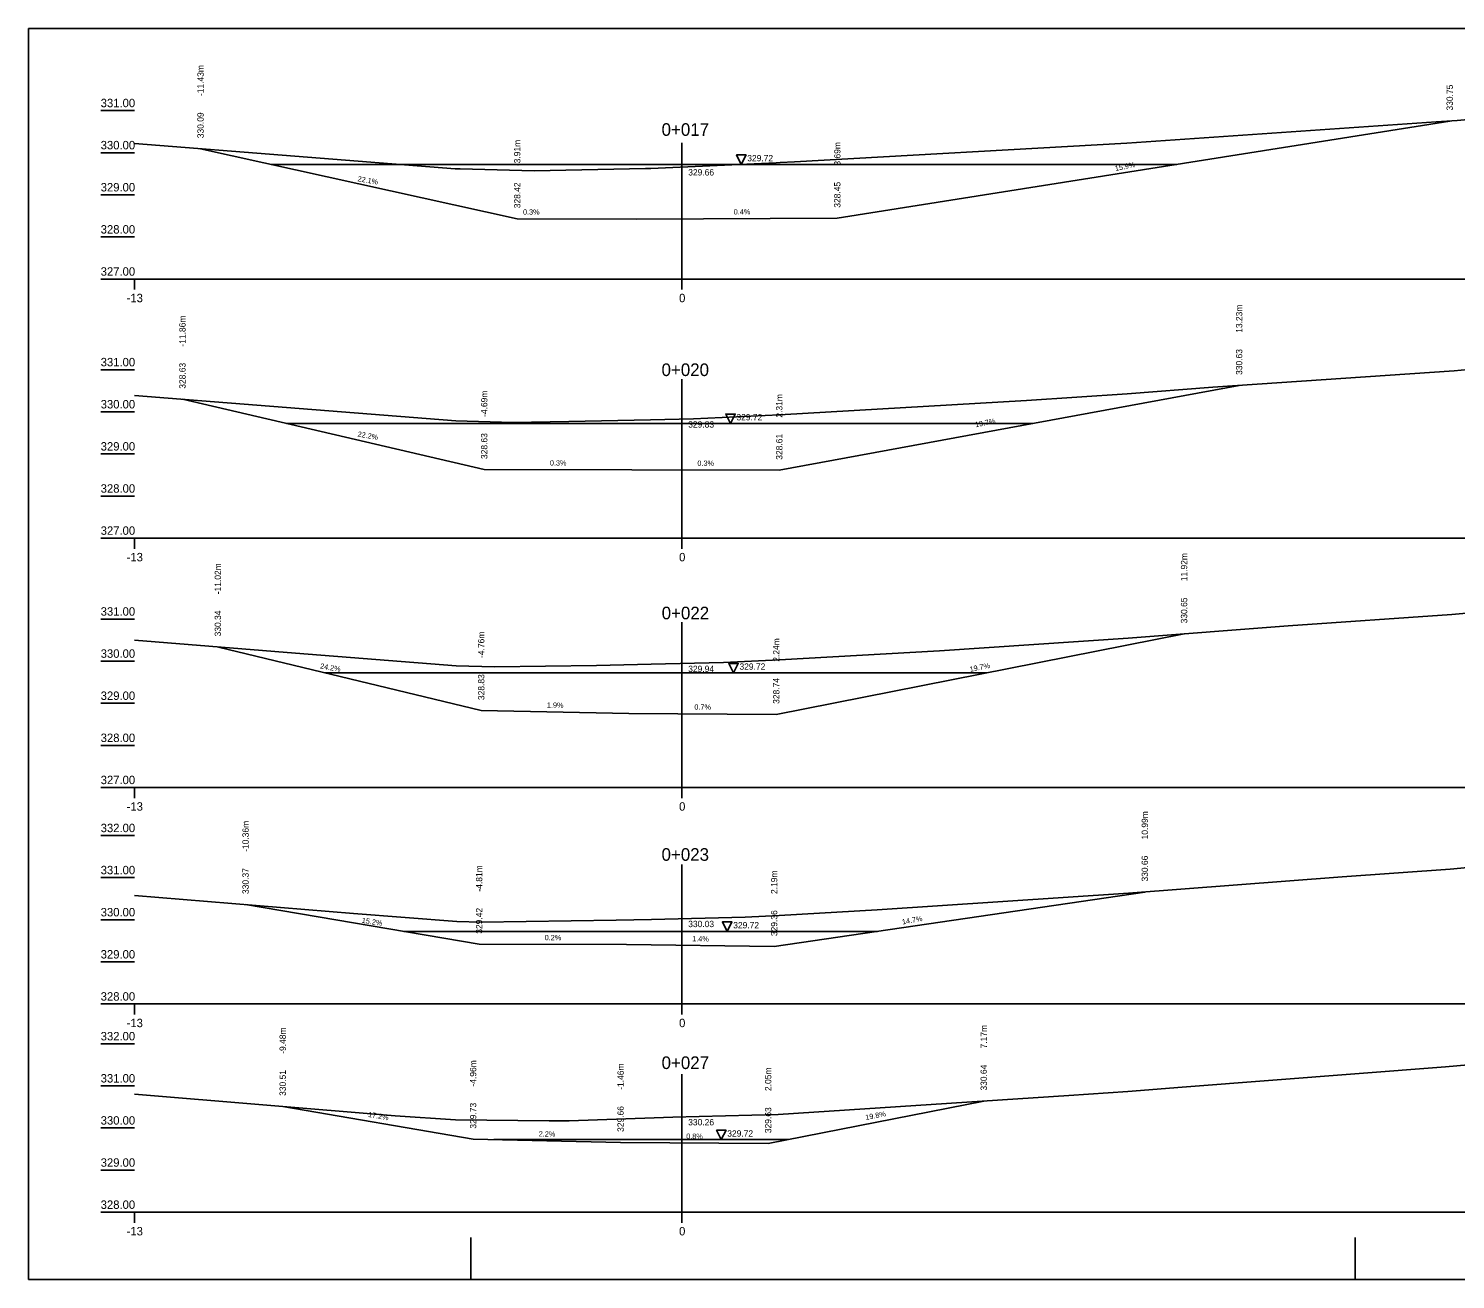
# Model space of a CAD drawing. Extents: x -557757.2 to -557704.7, y -1163075.9 to -1163046.2.
# Drawn here: x -557757.2 to -557723.32, y -1163075.94 to -1163046.24 of the extents above; entities that cross this region are included whole.
import ezdxf

# ---------------------------------------------------------------- set-up
doc = ezdxf.new("R2010")
doc.units = 0
for name, color, linetype in [('16', 7, 'Continuous'), ('21', 7, 'Continuous'), ('28', 7, 'Continuous'), ('59', 7, 'Continuous'), ('Body pricny rez', 7, 'Continuous'), ('Popis pricneho profilu', 7, 'Continuous')]:
    doc.layers.add(name, color=color, linetype=linetype)

msp = doc.modelspace()

# ---------------------------------------------------------------- linework, layer by layer
for p, q in [((-557704.7, -1163046.243), (-557757.2, -1163046.243)), ((-557757.2, -1163046.243), (-557757.2, -1163075.943)), ((-557746.7, -1163075.943), (-557746.7, -1163074.943)), ((-557725.7, -1163075.943), (-557725.7, -1163074.943)), ((-557757.2, -1163075.943), (-557704.7, -1163075.943))]:
    msp.add_line(p, q)
for points in [[(-557754.687, -1163048.974), (-557747.074, -1163049.572), (-557746.951, -1163049.573), (-557746.95, -1163049.573), (-557745.198, -1163049.623), (-557742.55, -1163049.568), (-557742.425, -1163049.567), (-557739.452, -1163049.428), (-557739.355, -1163049.423), (-557739.014, -1163049.405), (-557731.126, -1163048.962), (-557723.775, -1163048.462), (-557723.281, -1163048.428), (-557721.687, -1163048.284)], [(-557737.997, -1163050.747), (-557723.457, -1163048.44)], [(-557742.764, -1163050.767), (-557745.597, -1163050.76), (-557753.117, -1163049.097)], [(-557751.441, -1163049.468), (-557729.936, -1163049.468)], [(-557742.764, -1163050.767), (-557737.997, -1163050.747)], [(-557742.764, -1163050.767), (-557737.997, -1163050.747)], [(-557754.687, -1163054.952), (-557752.781, -1163055.108), (-557747.058, -1163055.556), (-557745.702, -1163055.595), (-557744.371, -1163055.575), (-557742.431, -1163055.534), (-557741.41, -1163055.51), (-557739.368, -1163055.414), (-557733.503, -1163055.076), (-557731.111, -1163054.918), (-557729.08, -1163054.759), (-557723.35, -1163054.37), (-557721.687, -1163054.213)], [(-557739.375, -1163056.731), (-557728.457, -1163054.717)], [(-557742.877, -1163056.723), (-557746.38, -1163056.714), (-557753.547, -1163055.045)], [(-557751.077, -1163055.62), (-557733.353, -1163055.62)], [(-557742.877, -1163056.723), (-557746.38, -1163056.714)], [(-557742.877, -1163056.723), (-557739.375, -1163056.731)], [(-557742.877, -1163056.723), (-557739.375, -1163056.731)], [(-557754.687, -1163060.763), (-557750.861, -1163061.076), (-557747.043, -1163061.376), (-557746.139, -1163061.401), (-557743.716, -1163061.365), (-557742.418, -1163061.338), (-557740.697, -1163061.298), (-557739.372, -1163061.235), (-557735.569, -1163061.016), (-557731.093, -1163060.72), (-557727.294, -1163060.423), (-557723.406, -1163060.159), (-557721.687, -1163059.997)], [(-557739.446, -1163062.527), (-557729.764, -1163060.616)], [(-557739.446, -1163062.527), (-557729.764, -1163060.616)], [(-557746.451, -1163062.437), (-557752.687, -1163060.927)], [(-557750.154, -1163061.54), (-557734.447, -1163061.54)], [(-557742.948, -1163062.502), (-557746.451, -1163062.437)], [(-557742.948, -1163062.502), (-557746.451, -1163062.437)], [(-557742.948, -1163062.502), (-557739.446, -1163062.527)], [(-557742.948, -1163062.502), (-557739.446, -1163062.527)], [(-557754.687, -1163066.825), (-557749.483, -1163067.251), (-557747.032, -1163067.443), (-557746.452, -1163067.459), (-557743.246, -1163067.412), (-557742.409, -1163067.395), (-557740.184, -1163067.343), (-557739.375, -1163067.304), (-557737.051, -1163067.171), (-557731.081, -1163066.775), (-557726.013, -1163066.38), (-557723.447, -1163066.205), (-557721.687, -1163066.039)], [(-557739.497, -1163068.041), (-557730.697, -1163066.745)], [(-557746.502, -1163067.984), (-557752.047, -1163067.041)], [(-557748.29, -1163067.68), (-557737.045, -1163067.68)], [(-557742.999, -1163067.992), (-557746.502, -1163067.984)], [(-557742.999, -1163067.992), (-557746.502, -1163067.984)], [(-557742.999, -1163067.992), (-557739.497, -1163068.041)], [(-557742.999, -1163067.992), (-557739.497, -1163068.041)], [(-557754.687, -1163071.547), (-557748.492, -1163072.055), (-557747.066, -1163072.157), (-557744.839, -1163072.175), (-557744.64, -1163072.177), (-557744.365, -1163072.179), (-557742.347, -1163072.108), (-557741.902, -1163072.09), (-557739.398, -1163072.03), (-557732.496, -1163071.574), (-557731.099, -1163071.478), (-557729.805, -1163071.381), (-557723.555, -1163070.894), (-557722.212, -1163070.775), (-557721.687, -1163070.726)], [(-557739.64, -1163072.719), (-557734.521, -1163071.708)], [(-557739.64, -1163072.719), (-557734.521, -1163071.708)], [(-557746.645, -1163072.613), (-557751.166, -1163071.835)], [(-557746.645, -1163072.613), (-557751.166, -1163071.835)], [(-557743.142, -1163072.69), (-557746.645, -1163072.613)], [(-557743.142, -1163072.69), (-557746.645, -1163072.613)], [(-557746.151, -1163072.624), (-557739.157, -1163072.624)], [(-557743.142, -1163072.69), (-557739.64, -1163072.719)], [(-557743.142, -1163072.69), (-557739.64, -1163072.719)]]:
    msp.add_lwpolyline(points)
for points in [[(-557740.277, -1163049.468), (-557740.389, -1163049.243), (-557740.164, -1163049.243)], [(-557740.534, -1163055.62), (-557740.647, -1163055.395), (-557740.422, -1163055.395)], [(-557740.463, -1163061.54), (-557740.575, -1163061.315), (-557740.35, -1163061.315)], [(-557740.61, -1163067.68), (-557740.723, -1163067.455), (-557740.498, -1163067.455)], [(-557740.752, -1163072.624), (-557740.864, -1163072.399), (-557740.639, -1163072.399)]]:
    msp.add_lwpolyline(points, close=True)
at = {"layer": '16'}
for p, q in [((-557754.687, -1163052.191), (-557721.687, -1163052.191)), ((-557754.687, -1163058.343), (-557721.687, -1163058.343)), ((-557754.687, -1163064.263), (-557721.687, -1163064.263)), ((-557754.687, -1163069.403), (-557721.687, -1163069.403)), ((-557754.687, -1163074.347), (-557721.687, -1163074.347))]:
    msp.add_line(p, q, dxfattribs=at)
at = {"layer": '21'}
for p, q in [((-557755.487, -1163048.191), (-557754.687, -1163048.191)), ((-557755.487, -1163049.191), (-557754.687, -1163049.191)), ((-557755.487, -1163050.191), (-557754.687, -1163050.191)), ((-557755.487, -1163051.191), (-557754.687, -1163051.191)), ((-557755.487, -1163052.191), (-557754.687, -1163052.191)), ((-557755.487, -1163054.343), (-557754.687, -1163054.343)), ((-557755.487, -1163055.343), (-557754.687, -1163055.343)), ((-557755.487, -1163056.343), (-557754.687, -1163056.343)), ((-557755.487, -1163057.343), (-557754.687, -1163057.343)), ((-557755.487, -1163058.343), (-557754.687, -1163058.343)), ((-557755.487, -1163060.263), (-557754.687, -1163060.263)), ((-557755.487, -1163061.263), (-557754.687, -1163061.263)), ((-557755.487, -1163062.263), (-557754.687, -1163062.263)), ((-557755.487, -1163063.263), (-557754.687, -1163063.263)), ((-557755.487, -1163064.263), (-557754.687, -1163064.263)), ((-557755.487, -1163065.403), (-557754.687, -1163065.403)), ((-557755.487, -1163066.403), (-557754.687, -1163066.403)), ((-557755.487, -1163067.403), (-557754.687, -1163067.403)), ((-557755.487, -1163068.403), (-557754.687, -1163068.403)), ((-557755.487, -1163069.403), (-557754.687, -1163069.403)), ((-557755.487, -1163070.347), (-557754.687, -1163070.347)), ((-557755.487, -1163071.347), (-557754.687, -1163071.347)), ((-557755.487, -1163072.347), (-557754.687, -1163072.347)), ((-557755.487, -1163073.347), (-557754.687, -1163073.347)), ((-557755.487, -1163074.347), (-557754.687, -1163074.347))]:
    msp.add_line(p, q, dxfattribs=at)
at = {"layer": '28'}
for p, q in [((-557741.687, -1163048.957), (-557741.687, -1163052.191)), ((-557741.687, -1163054.57), (-557741.687, -1163058.343)), ((-557741.687, -1163060.337), (-557741.687, -1163064.263)), ((-557741.687, -1163066.087), (-557741.687, -1163069.403)), ((-557741.687, -1163071.065), (-557741.687, -1163074.347))]:
    msp.add_line(p, q, dxfattribs=at)
at = {"layer": '59'}
for p, q in [((-557754.687, -1163052.441), (-557754.687, -1163052.191)), ((-557741.687, -1163052.441), (-557741.687, -1163052.191)), ((-557754.687, -1163058.593), (-557754.687, -1163058.343)), ((-557741.687, -1163058.593), (-557741.687, -1163058.343)), ((-557754.687, -1163064.513), (-557754.687, -1163064.263)), ((-557741.687, -1163064.513), (-557741.687, -1163064.263)), ((-557754.687, -1163069.653), (-557754.687, -1163069.403)), ((-557741.687, -1163069.653), (-557741.687, -1163069.403)), ((-557754.687, -1163074.597), (-557754.687, -1163074.347)), ((-557741.687, -1163074.597), (-557741.687, -1163074.347))]:
    msp.add_line(p, q, dxfattribs=at)

# ---------------------------------------------------------------- texts
for s, height, p in [('0+017', 0.3, (-557742.169, -1163048.791)), ('329.72', 0.15, (-557740.135, -1163049.395)), ('0+020', 0.3, (-557742.17, -1163054.494)), ('329.72', 0.15, (-557740.392, -1163055.547)), ('0+022', 0.3, (-557742.167, -1163060.27)), ('329.72', 0.15, (-557740.32, -1163061.467)), ('0+023', 0.3, (-557742.17, -1163066.003)), ('329.72', 0.15, (-557740.468, -1163067.607)), ('0+027', 0.3, (-557742.169, -1163070.947)), ('329.72', 0.15, (-557740.61, -1163072.551))]:
    msp.add_text(s, height=height).set_placement(p)
msp.add_text('15.9%', height=0.125, rotation=11.6169).set_placement((-557731.394, -1163049.628))
at = {"layer": '16'}
for s, rotation, p in [('22.1%', 350.2446, (-557749.395, -1163049.867)), ('0.3%', 359.8567, (-557745.46, -1163050.661)), ('0.4%', 0.2449, (-557740.456, -1163050.658)), ('19.7%', 11.1642, (-557734.715, -1163055.712)), ('22.2%', 350.2446, (-557749.395, -1163055.929)), ('0.3%', 359.8567, (-557744.822, -1163056.618)), ('0.3%', 359.8567, (-557741.319, -1163056.626)), ('24.2%', 350.4315, (-557750.284, -1163061.436)), ('19.7%', 11.1642, (-557734.842, -1163061.518)), ('1.9%', 358.9299, (-557744.893, -1163062.366)), ('0.7%', 359.5993, (-557741.391, -1163062.413)), ('14.7%', 10.2693, (-557736.45, -1163067.517)), ('15.2%', 351.3494, (-557749.294, -1163067.475)), ('0.2%', 359.8713, (-557744.944, -1163067.888)), ('1.4%', 359.1981, (-557741.442, -1163067.914)), ('17.2%', 350.2446, (-557749.144, -1163072.083)), ('19.8%', 11.1782, (-557737.318, -1163072.16)), ('2.2%', 358.7376, (-557745.087, -1163072.547)), ('0.8%', 359.525, (-557741.585, -1163072.603))]:
    msp.add_text(s, height=0.125, rotation=rotation, dxfattribs=at).set_placement(p)
at = {"layer": '21'}
for s, p in [('331.00', (-557755.487, -1163048.111)), ('330.00', (-557755.487, -1163049.111)), ('329.00', (-557755.487, -1163050.111)), ('328.00', (-557755.487, -1163051.111)), ('327.00', (-557755.487, -1163052.111)), ('-13', (-557754.871, -1163052.741)), ('0', (-557741.754, -1163052.741)), ('331.00', (-557755.487, -1163054.263)), ('330.00', (-557755.487, -1163055.263)), ('329.00', (-557755.487, -1163056.263)), ('328.00', (-557755.487, -1163057.263)), ('327.00', (-557755.487, -1163058.263)), ('-13', (-557754.871, -1163058.893)), ('0', (-557741.754, -1163058.893)), ('331.00', (-557755.487, -1163060.183)), ('330.00', (-557755.487, -1163061.183)), ('329.00', (-557755.487, -1163062.183)), ('328.00', (-557755.487, -1163063.183)), ('327.00', (-557755.487, -1163064.183)), ('-13', (-557754.871, -1163064.813)), ('0', (-557741.754, -1163064.813)), ('332.00', (-557755.487, -1163065.323)), ('331.00', (-557755.487, -1163066.323)), ('330.00', (-557755.487, -1163067.323)), ('329.00', (-557755.487, -1163068.323)), ('328.00', (-557755.487, -1163069.323)), ('-13', (-557754.871, -1163069.953)), ('0', (-557741.754, -1163069.953)), ('332.00', (-557755.487, -1163070.267)), ('331.00', (-557755.487, -1163071.267)), ('330.00', (-557755.487, -1163072.267)), ('329.00', (-557755.487, -1163073.267)), ('328.00', (-557755.487, -1163074.267)), ('-13', (-557754.871, -1163074.897)), ('0', (-557741.754, -1163074.897))]:
    msp.add_text(s, height=0.2, dxfattribs=at).set_placement(p)
at = {"layer": '59'}
for s, p in [('329.66', (-557741.537, -1163049.732)), ('329.83', (-557741.537, -1163055.717)), ('329.94', (-557741.537, -1163061.521)), ('330.03', (-557741.537, -1163067.578)), ('330.26', (-557741.537, -1163072.285))]:
    msp.add_text(s, height=0.15, dxfattribs=at).set_placement(p)
at = {"layer": 'Body pricny rez'}
for p in [(-557723.457, -1163048.441), (-557723.457, -1163048.441), (-557727.56, -1163048.72), (-557752.614, -1163049.138), (-557742.765, -1163050.768), (-557742.765, -1163050.768), (-557729.582, -1163054.799), (-557729.582, -1163054.799), (-557746.38, -1163056.714), (-557746.38, -1163056.714), (-557742.878, -1163056.723), (-557742.878, -1163056.723), (-557739.375, -1163056.732), (-557739.375, -1163056.732), (-557729.764, -1163060.617), (-557729.764, -1163060.617), (-557752.707, -1163060.926), (-557752.707, -1163060.926), (-557746.451, -1163062.437), (-557746.451, -1163062.437), (-557742.949, -1163062.503), (-557742.949, -1163062.503), (-557739.446, -1163062.527), (-557739.446, -1163062.527), (-557730.697, -1163066.746), (-557730.697, -1163066.746), (-557752.047, -1163067.041), (-557752.047, -1163067.041), (-557746.502, -1163067.985), (-557746.502, -1163067.985), (-557743, -1163067.993), (-557743, -1163067.993), (-557739.497, -1163068.042), (-557739.497, -1163068.042), (-557734.521, -1163071.708), (-557734.521, -1163071.708), (-557751.167, -1163071.836), (-557751.167, -1163071.836), (-557746.645, -1163072.613), (-557746.645, -1163072.613), (-557743.143, -1163072.691), (-557743.143, -1163072.691), (-557739.64, -1163072.72), (-557739.64, -1163072.72)]:
    msp.add_text('+', height=0.001, dxfattribs=at).set_placement(p)
at = {"layer": 'Popis pricneho profilu'}
for s, p in [('-11.43m', (-557753.042, -1163047.847)), ('330.75', (-557723.382, -1163048.19)), ('330.09', (-557753.042, -1163048.847)), ('-3.91m', (-557745.522, -1163049.51)), ('3.69m', (-557737.922, -1163049.497)), ('328.42', (-557745.522, -1163050.51)), ('328.45', (-557737.922, -1163050.497)), ('-11.86m', (-557753.472, -1163053.795)), ('13.23m', (-557728.382, -1163053.467)), ('330.63', (-557728.382, -1163054.467)), ('328.63', (-557753.472, -1163054.795)), ('-4.69m', (-557746.305, -1163055.464)), ('2.31m', (-557739.3, -1163055.481)), ('328.63', (-557746.305, -1163056.464)), ('328.61', (-557739.3, -1163056.481)), ('11.92m', (-557729.689, -1163059.366)), ('-11.02m', (-557752.632, -1163059.675)), ('330.65', (-557729.689, -1163060.366)), ('330.34', (-557752.632, -1163060.675)), ('-4.76m', (-557746.376, -1163061.187)), ('2.24m', (-557739.371, -1163061.277)), ('328.83', (-557746.376, -1163062.187)), ('328.74', (-557739.371, -1163062.277)), ('10.99m', (-557730.622, -1163065.495)), ('-10.36m', (-557751.972, -1163065.791)), ('330.66', (-557730.622, -1163066.495)), ('330.37', (-557751.972, -1163066.791)), ('-4.81m', (-557746.427, -1163066.734)), ('2.19m', (-557739.422, -1163066.791)), ('329.42', (-557746.427, -1163067.734)), ('329.36', (-557739.422, -1163067.791)), ('-9.48m', (-557751.091, -1163070.585)), ('7.17m', (-557734.446, -1163070.458)), ('330.51', (-557751.091, -1163071.585)), ('-4.96m', (-557746.57, -1163071.363)), ('-1.46m', (-557743.067, -1163071.44)), ('2.05m', (-557739.565, -1163071.469)), ('330.64', (-557734.446, -1163071.458)), ('329.73', (-557746.57, -1163072.363)), ('329.66', (-557743.067, -1163072.44)), ('329.63', (-557739.565, -1163072.469))]:
    msp.add_text(s, height=0.15, rotation=90, dxfattribs=at).set_placement(p)

doc.saveas('drawing.dxf')
